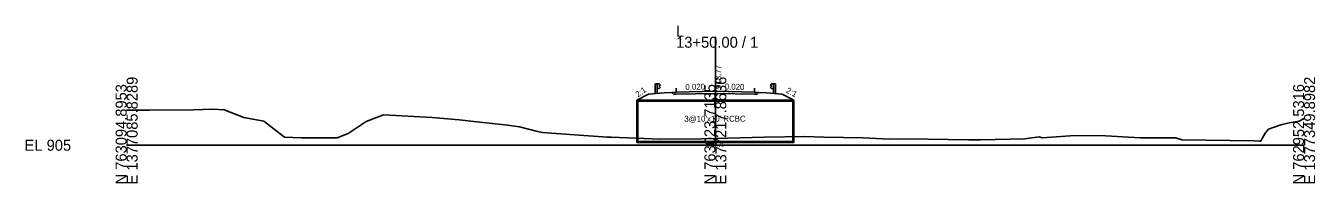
# Model space of a CAD drawing. Extents: x -26 to 303, y -10 to 6523.
# Drawn here: x -25.7 to 302.8, y 3490.3 to 3530.5 of the extents above; entities that cross this region are included whole.
import ezdxf

# ---------------------------------------------------------------- set-up
doc = ezdxf.new("R2010")
doc.units = 0
for name, color, linetype in [('Exist Cross Section Cell', 7, 'Continuous'), ('Exist XS Center Line Elevation Label', 7, 'Continuous'), ('Exist XS Ground Line', 7, 'Continuous'), ('Prop XS Dump Level', 7, 'Continuous'), ('Prop XS Elevation Labels', 7, 'Continuous'), ('Prop XS EOT Tick Mark', 7, 'Continuous'), ('Prop XS Finish Grade', 7, 'Continuous'), ('Prop XS Finish Grade Earthwork', 7, 'Continuous'), ('Prop XS Finish Grade Pavement', 7, 'Continuous'), ('Prop XS Guardrail', 7, 'Continuous'), ('Prop XS Pvmt Edge Slope', 7, 'Continuous'), ('Prop XS SE Text', 7, 'Continuous'), ('Prop XS Side Slope Text', 7, 'Continuous'), ('Prop XS Subgrade Earthwork', 7, 'Continuous')]:
    doc.layers.add(name, color=color, linetype=linetype)

msp = doc.modelspace()

# ---------------------------------------------------------------- linework, layer by layer
at = {"layer": 'Exist Cross Section Cell'}
for p, q in [((150, 3500), (150, 3527.68)), ((0, 3500), (150, 3500)), ((150, 3500), (300, 3500))]:
    msp.add_line(p, q, dxfattribs=at)
at = {"layer": 'Exist XS Ground Line'}
for p, q in [((0, 3508.94), (5.79, 3508.93)), ((5.79, 3508.93), (17.07, 3509.06)), ((17.07, 3509.06), (22, 3509.23)), ((22, 3509.23), (24.81, 3509.03)), ((24.81, 3509.03), (29.88, 3507.09)), ((29.88, 3507.09), (34.97, 3506.15)), ((34.97, 3506.15), (40.26, 3502.05)), ((56.44, 3502.96), (61.02, 3506.04)), ((61.02, 3506.04), (65.45, 3507.8)), ((65.45, 3507.8), (77.81, 3507.09)), ((77.81, 3507.09), (84.69, 3506.51)), ((84.69, 3506.51), (89.22, 3506)), ((89.22, 3506), (97.04, 3505.14)), ((294.12, 3505.24), (296.23, 3505.69)), ((296.23, 3505.69), (298.78, 3506.14)), ((298.78, 3506.14), (300, 3506.86)), ((53.62, 3501.88), (56.44, 3502.96)), ((97.04, 3505.14), (100.06, 3504.72)), ((100.06, 3504.72), (104.66, 3503.48)), ((104.66, 3503.48), (105.93, 3503.26)), ((105.93, 3503.26), (114.13, 3502.69)), ((114.13, 3502.69), (122.56, 3502.07)), ((162.56, 3502.09), (172.77, 3502.2)), ((172.77, 3502.2), (177.65, 3502.1)), ((228.84, 3501.62), (232.52, 3502.18)), ((232.52, 3502.18), (233.26, 3501.89)), ((233.26, 3501.89), (240.43, 3502.39)), ((240.43, 3502.39), (247.99, 3502.46)), ((247.99, 3502.46), (258.2, 3501.88)), ((289.39, 3501.88), (290.11, 3503.06)), ((290.11, 3503.06), (290.93, 3504.1)), ((290.93, 3504.1), (294.12, 3505.24)), ((40.26, 3502.05), (44.55, 3501.9)), ((44.55, 3501.9), (53.62, 3501.88)), ((122.56, 3502.07), (123.42, 3502.04)), ((123.42, 3502.04), (135.91, 3501.55)), ((135.91, 3501.55), (146.48, 3501.6)), ((146.48, 3501.6), (150, 3501.71)), ((150, 3501.71), (162.56, 3502.09)), ((177.65, 3502.1), (187.69, 3501.89)), ((187.69, 3501.89), (194.47, 3501.56)), ((194.47, 3501.56), (199.08, 3501.66)), ((199.08, 3501.66), (214.47, 3501.37)), ((214.47, 3501.37), (217.57, 3501.36)), ((217.57, 3501.36), (228.84, 3501.62)), ((258.2, 3501.88), (261.21, 3501.85)), ((261.21, 3501.85), (267.24, 3501.89)), ((267.24, 3501.89), (268.98, 3501.39)), ((268.98, 3501.39), (287.19, 3501.16)), ((287.19, 3501.16), (288.61, 3501.03)), ((288.61, 3501.03), (289, 3501.02)), ((289, 3501.02), (289.39, 3501.88))]:
    msp.add_line(p, q, dxfattribs=at)
at = {"layer": 'Prop XS Dump Level'}
for p, q in [((140, 3513.57), (150, 3513.77)), ((150, 3513.77), (160, 3513.57))]:
    msp.add_line(p, q, dxfattribs=at)
at = {"layer": 'Prop XS EOT Tick Mark'}
for p, q in [((140, 3513.57), (140, 3514.57)), ((160, 3513.57), (160, 3514.57))]:
    msp.add_line(p, q, dxfattribs=at)
at = {"layer": 'Prop XS Finish Grade'}
for p, q in [((140, 3513.57), (138.9, 3513.48)), ((160, 3513.57), (161.1, 3513.48))]:
    msp.add_line(p, q, dxfattribs=at)
at = {"layer": 'Prop XS Finish Grade Earthwork'}
for p, q in [((133, 3513.01), (130, 3511.51)), ((137, 3513.33), (133, 3513.01)), ((138.9, 3513.48), (137, 3513.33)), ((161.1, 3513.48), (163, 3513.33)), ((163, 3513.33), (167, 3513.01)), ((170, 3511.51), (167, 3513.01)), ((170, 3511.51), (130, 3511.51)), ((130, 3511.51), (170, 3511.51)), ((130, 3511.51), (130, 3500.71)), ((130.25, 3511.26), (130.25, 3500.96)), ((130.25, 3511.26), (169.75, 3511.26)), ((169.75, 3511.26), (169.75, 3500.96)), ((170, 3511.51), (170, 3500.71)), ((130, 3500.71), (170, 3500.71)), ((130.25, 3500.96), (169.75, 3500.96))]:
    msp.add_line(p, q, dxfattribs=at)
at = {"layer": 'Prop XS Finish Grade Pavement'}
for p, q in [((140, 3513.57), (150, 3513.77)), ((150, 3513.77), (160, 3513.57))]:
    msp.add_line(p, q, dxfattribs=at)
at = {"layer": 'Prop XS Guardrail'}
for p, q in [((134.68, 3515.65), (135.18, 3515.65)), ((134.68, 3513.15), (134.68, 3515.65)), ((135.18, 3515.65), (135.68, 3515.65)), ((135.18, 3515.65), (135.18, 3513.15)), ((135.68, 3515.65), (135.97, 3515.45)), ((135.97, 3515.33), (135.68, 3515.13)), ((135.97, 3515.45), (136, 3515.39)), ((136, 3515.39), (135.97, 3515.33)), ((164.03, 3515.45), (164, 3515.39)), ((164, 3515.39), (164.03, 3515.33)), ((164.32, 3515.65), (164.03, 3515.45)), ((164.03, 3515.33), (164.32, 3515.13)), ((164.82, 3515.65), (164.32, 3515.65)), ((165.32, 3515.65), (164.82, 3515.65)), ((164.82, 3515.65), (164.82, 3513.15)), ((165.32, 3513.15), (165.32, 3515.65)), ((135.68, 3514.51), (135.18, 3514.51)), ((135.68, 3515.13), (135.68, 3515.03)), ((135.68, 3515.03), (135.97, 3514.83)), ((135.97, 3514.71), (135.68, 3514.51)), ((135.97, 3514.83), (136, 3514.77)), ((136, 3514.77), (135.97, 3514.71)), ((164.03, 3514.83), (164, 3514.77)), ((164, 3514.77), (164.03, 3514.71)), ((164.32, 3515.03), (164.03, 3514.83)), ((164.03, 3514.71), (164.32, 3514.51)), ((164.32, 3515.13), (164.32, 3515.03)), ((164.32, 3514.51), (164.82, 3514.51))]:
    msp.add_line(p, q, dxfattribs=at)
at = {"layer": 'Prop XS Pvmt Edge Slope'}
for p, q in [((140, 3513.57), (139.4, 3512.98)), ((160, 3513.57), (160.6, 3512.98))]:
    msp.add_line(p, q, dxfattribs=at)
at = {"layer": 'Prop XS Subgrade Earthwork'}
for p, q in [((139.4, 3512.98), (138.9, 3513.48)), ((140, 3512.99), (139.4, 3512.98)), ((150, 3513.19), (140, 3512.99)), ((160, 3512.99), (150, 3513.19)), ((160, 3512.99), (160.6, 3512.98)), ((160.6, 3512.98), (161.1, 3513.48))]:
    msp.add_line(p, q, dxfattribs=at)

# ---------------------------------------------------------------- texts
at = {"layer": 'Exist Cross Section Cell'}
for s, p in [('L', (140, 3527.68)), ('13+50.00 / 1', (140, 3524.88)), ('EL 905', (-26, 3498.6))]:
    msp.add_text(s, height=2.8, dxfattribs=at).set_placement(p)
for s, p in [('N 763094.8953', (0, 3490)), ('E 1377085.8289', (2.8, 3490)), ('N 763023.7135', (150, 3490)), ('E 1377217.8636', (152.8, 3490)), ('N 762952.5316', (300, 3490)), ('E 1377349.8982', (302.8, 3490))]:
    msp.add_text(s, height=2.8, rotation=90, dxfattribs=at).set_placement(p)
at = {"layer": 'Exist XS Center Line Elevation Label'}
msp.add_text('906.71', height=1.075, dxfattribs=at).set_placement((147.76, 3499.52))
at = {"layer": 'Prop XS Dump Level'}
for p in [(137, 3513.29), (163, 3513.29)]:
    msp.add_text('Case1', height=0.04, dxfattribs=at).set_placement(p)
at = {"layer": 'Prop XS Elevation Labels'}
msp.add_text(' 918.77', height=1.5, rotation=90, dxfattribs=at).set_placement((151.5, 3513.77))
at = {"layer": 'Prop XS SE Text'}
for rotation, p in [(1.1458, (142.38, 3514.12)), (358.8542, (152.38, 3514.22))]:
    msp.add_text('0.020', height=1.5, rotation=rotation, dxfattribs=at).set_placement(p)
msp.add_text("3@10'x10' RCBC", height=1.5, dxfattribs=at).set_placement((142.1, 3506.01))
at = {"layer": 'Prop XS Side Slope Text'}
for rotation, p in [(35.0153, (130.28, 3512.18)), (331.1235, (167.87, 3513.53))]:
    msp.add_text('2:1', height=1.5, rotation=rotation, dxfattribs=at).set_placement(p)

doc.saveas('drawing.dxf')
